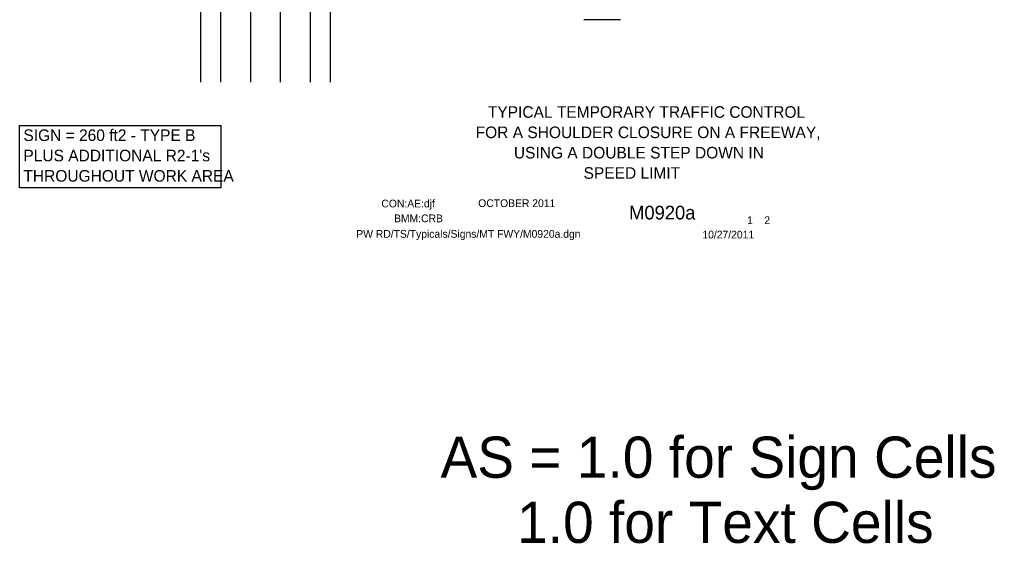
# Model space of a CAD drawing. Extents: x 16737 to 18479, y 6975 to 8225.
# Drawn here: x 16801 to 17582, y 6975 to 7395 of the extents above; entities that cross this region are included whole.
import ezdxf

# ---------------------------------------------------------------- set-up
doc = ezdxf.new("R2010")
doc.units = 0
for name, color, linetype in [('BORDER', 7, 'Continuous'), ('BORDER_SIGNAL_WO', 7, 'Continuous'), ('PAVT_EDGE_EX', 7, 'Continuous'), ('TYPICAL_TEXT_DIMEN_EX', 7, 'Continuous'), ('TYPICAL_TEXT_DIMEN_PR', 7, 'Continuous')]:
    doc.layers.add(name, color=color, linetype=linetype)

msp = doc.modelspace()

# ---------------------------------------------------------------- linework, layer by layer
at = {"layer": 'PAVT_EDGE_EX'}
for p, q in [((16985.65, 8211.96), (16985.65, 7344.79)), ((17009.65, 8211.96), (17009.65, 7344.79)), ((16985.65, 8097.28), (16985.65, 7344.79)), ((17009.65, 8097.28), (17009.65, 7344.79)), ((16945.65, 7942.5), (16945.65, 7344.79)), ((16961.65, 7942.41), (16961.65, 7344.79)), ((17033.65, 7942.16), (17033.65, 7344.79)), ((17049.65, 7942.41), (17049.65, 7344.79))]:
    msp.add_line(p, q, dxfattribs=at)
at = {"layer": 'TYPICAL_TEXT_DIMEN_EX'}
msp.add_lwpolyline([(16800.62, 7309.98), (16962.02, 7309.98), (16962.02, 7259.91), (16800.62, 7259.91)], close=True, dxfattribs=at)
at = {"layer": 'TYPICAL_TEXT_DIMEN_PR'}
msp.add_line((17282.35, 7394.76), (17252.91, 7394.76), dxfattribs=at)

# ---------------------------------------------------------------- texts
at = {"layer": 'BORDER'}
for s, p in [('TYPICAL TEMPORARY TRAFFIC CONTROL', (17176.01, 7316.16)), ('FOR A SHOULDER CLOSURE ON A FREEWAY,', (17166.21, 7299.86)), ('USING A DOUBLE STEP DOWN IN', (17196.85, 7283.56)), ('SPEED LIMIT', (17252.72, 7267.26))]:
    msp.add_text(s, height=9.3, dxfattribs=at).set_placement(p)
at = {"layer": 'BORDER_SIGNAL_WO'}
for s, height, p in [('CON:AE:djf  ', 6.2, (17090.69, 7244.31)), ('    OCTOBER 2011    ', 6.2, (17159.08, 7244.59)), ('    M0920a   ', 11, (17272.86, 7234.63)), ('BMM:CRB   ', 6.2, (17100.81, 7232.42)), (' 1    2 ', 6.2, (17381.45, 7230.95)), ('PW RD/TS/Typicals/Signs/MT FWY/M0920a.dgn      ', 6.2, (17070.55, 7219.96)), ('10/27/2011    ', 6.2, (17347.93, 7219.38)), ('AS = 1.0 for Sign Cells', 33.0301, (17138.06, 7027.47)), ('     1.0 for Text Cells', 33.0301, (17138.06, 6975.24))]:
    msp.add_text(s, height=height, dxfattribs=at).set_placement(p)
at = {"layer": 'TYPICAL_TEXT_DIMEN_EX'}
for s, p in [('SIGN = 260 ft2 - TYPE B', (16803.75, 7297.56)), ("PLUS ADDITIONAL R2-1's", (16803.75, 7281.26)), ('THROUGHOUT WORK AREA', (16803.75, 7264.96))]:
    msp.add_text(s, height=9.3, dxfattribs=at).set_placement(p)

doc.saveas('drawing.dxf')
